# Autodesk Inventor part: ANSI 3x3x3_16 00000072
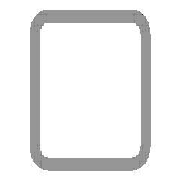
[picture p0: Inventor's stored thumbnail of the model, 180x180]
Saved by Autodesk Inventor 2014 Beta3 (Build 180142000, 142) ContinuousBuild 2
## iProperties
IsCustomPart: 1
_CCFamilyMember: 9
_CCFamilyDisplayName: ANSI AISC (Square) - Tube
_FrameMemberDoc: Frame Member File
_Version: 15.0.0
_GetPNFromCC: 1
Created: 2011-01
Part Number: ANSI 3x3x3_16 00000072
Material: Steel, Mild
Description: Tube
Document SubType Name: Modeling
Standard: ANSI
Designer: Beta-8540w
Standards Organization: ANSI
Language: en-US
Size Designation: 3x3x3/16
Categories: <MemberInstance><Categories><Category DisplayName="Structural Shapes" InternalName="089c4875-fa83-4c05-b084-43b9cc11f5ed" Mnemonic="GRDR"><CategoryParameter Dis
Stock Number: 3x3x3/16
Density: 7.86 g/cm^3
Appearance: Steel
G_L: 28.000 in
G_W: 3.000 in
G_H: 3.000 in
Author: Beta-8540w
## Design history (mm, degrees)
node "Start plane"
node "End plane"
sketch "Sketch"
  geometry: L1 (-38.1, -28.575)-(-38.1, 28.575); L2 (-28.575, 38.1)-(28.575, 38.1); L3 (38.1, 28.575)-(38.1, -28.575); L4 (28.575, -38.1)-(-28.575, -38.1); L5 (-28.575, 33.337)-(28.575, 33.338); L6 (33.338, 28.575)-(33.338, -28.575); L7 (28.575, -33.337)-(-28.575, -33.338); L8 (-33.338, -28.575)-(-33.338, 28.575); L9 (0, 56.102)-(0, -56.102) reference; L10 (-56.102, 0)-(56.102, 0) reference; A1 r 9.525 centre (-28.575, -28.575) between (-38.1, -28.575) and (-28.575, -38.1); A2 r 9.525 centre (-28.575, 28.575) between (-28.575, 38.1) and (-38.1, 28.575); A3 r 9.525 centre (28.575, 28.575) between (38.1, 28.575) and (28.575, 38.1); A4 r 9.525 centre (28.575, -28.575) between (28.575, -38.1) and (38.1, -28.575); A5 r 4.763 centre (-28.575, 28.575) between (-28.575, 33.337) and (-33.338, 28.575); A6 r 4.763 centre (28.575, 28.575) between (33.338, 28.575) and (28.575, 33.338); A7 r 4.763 centre (28.575, -28.575) between (28.575, -33.337) and (33.338, -28.575); A8 r 4.763 centre (-28.575, -28.575) between (-33.338, -28.575) and (-28.575, -33.338)
  constraints: 16 end point, 16 point on circle, 8 centre point, 8 tangent, 4 parallel, 3 equal radius, 2 perpendicular, 7 other
  dimensions: "d10" = 76.2 distance between parallel lines of L2 L4 (= G_H); "d11" = 76.2 distance between parallel lines of L1 L3 (= G_W); "d12" = 4.7625 distance between parallel lines of L3 L6 (= G_T); "d15" = 38.1 distance between parallel lines of L2 L10 (= 0.5 x d10); "d16" = 38.1 distance between parallel lines of L9 L3 (= 0.5 x d11); "d17" = 9.525 radius of A1 (= G_IR)
extrude "Body" new body sketch "Sketch" stored distance "d3" = 711.2 (= G_L); taper "d4" = 0 deg
node "Driven Length"
  sketch "Sketch3"
    geometry: L1 (0, 0)-(10, 0) reference
    constraints: 2 end point, 1 horizontal
  workplane "Work Plane3"
  sketch "Sketch4"
    geometry: L1 (-2, 0)-(12, 0) reference; L2 (-2, 711.2)-(12, 711.2) reference
    dimensions: "d19" = 711.2 distance between parallel lines of L1 L2 (derived)
body "Solid1"
other parameters: "G_W" = 76.2 [user parameter; used in 1 equation term], "G_H" = 76.2 [user parameter; used in 1 equation term], "G_T" = 4.7625 [user parameter; used in 1 equation term], "G_IR" = 9.525 [user parameter; used in 1 equation term], "G_L" = 711.2 (= d19) [user parameter; used in 1 equation term], "G_OFFSET_START" = 0 [user parameter; used in 1 equation term], "G_OFFSET_END" = 0 [user parameter; used in 1 equation term], "d13" = 0 (computed from G_OFFSET_START), "d14" = 711.2 (= G_OFFSET_END + B_L), "B_L" = 711.2 [user parameter; used in 1 equation term], "d18" = 90 deg
